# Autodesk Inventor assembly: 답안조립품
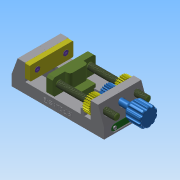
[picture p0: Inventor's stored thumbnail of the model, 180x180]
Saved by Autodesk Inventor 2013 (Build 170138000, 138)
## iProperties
Created: 2017-04
Part Number: 답안조립품
Document SubType Name: Assembly
Designer: Administrator
Mass: 1269.82 g
Surface Area: 784.418 cm^2
Volume: 280.832 cm^3
Density: 4.52165 g/cm^3
Author: Administrator
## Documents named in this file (10)
- C:\Users\Administrator\Desktop\370408V1018\답안조립품.iam
- C:\Users\Administrator\Desktop\370408V1018\370408V1018\바이스본체 A.ipt
- C:\Users\Administrator\Desktop\370408V1018\370408V1018\바이스본체 B.ipt
- C:\Users\Administrator\Desktop\370408V1018\370408V1018\슬라이딩 부품.ipt
- C:\Users\Administrator\Desktop\370408V1018\370408V1018\고정 플레이트.ipt
- C:\Users\Administrator\Desktop\370408V1018\370408V1018\십자오목머리나사 M3.ipt
- C:\Users\Administrator\Desktop\370408V1018\370408V1018\지지대.ipt
- C:\Users\Administrator\Desktop\370408V1018\370408V1018\십자오목머리나사 M4.ipt
- C:\Users\Administrator\Desktop\370408V1018\370408V1018\스퍼기어.ipt
- C:\Users\Administrator\Desktop\370408V1018\370408V1018\핸들.ipt
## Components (3 placed, 2 different names)
1. 고정 플레이트:1 — 각도:1
2. 고정 플레이트:2 — 각도:2
3. 핸들:1 — 구동
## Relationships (3: Angle 3)
- 각도:1 [Angle]: 고정 플레이트:1
- 각도:2 [Angle]: 고정 플레이트:2
- 구동 [Angle]: 핸들:1
